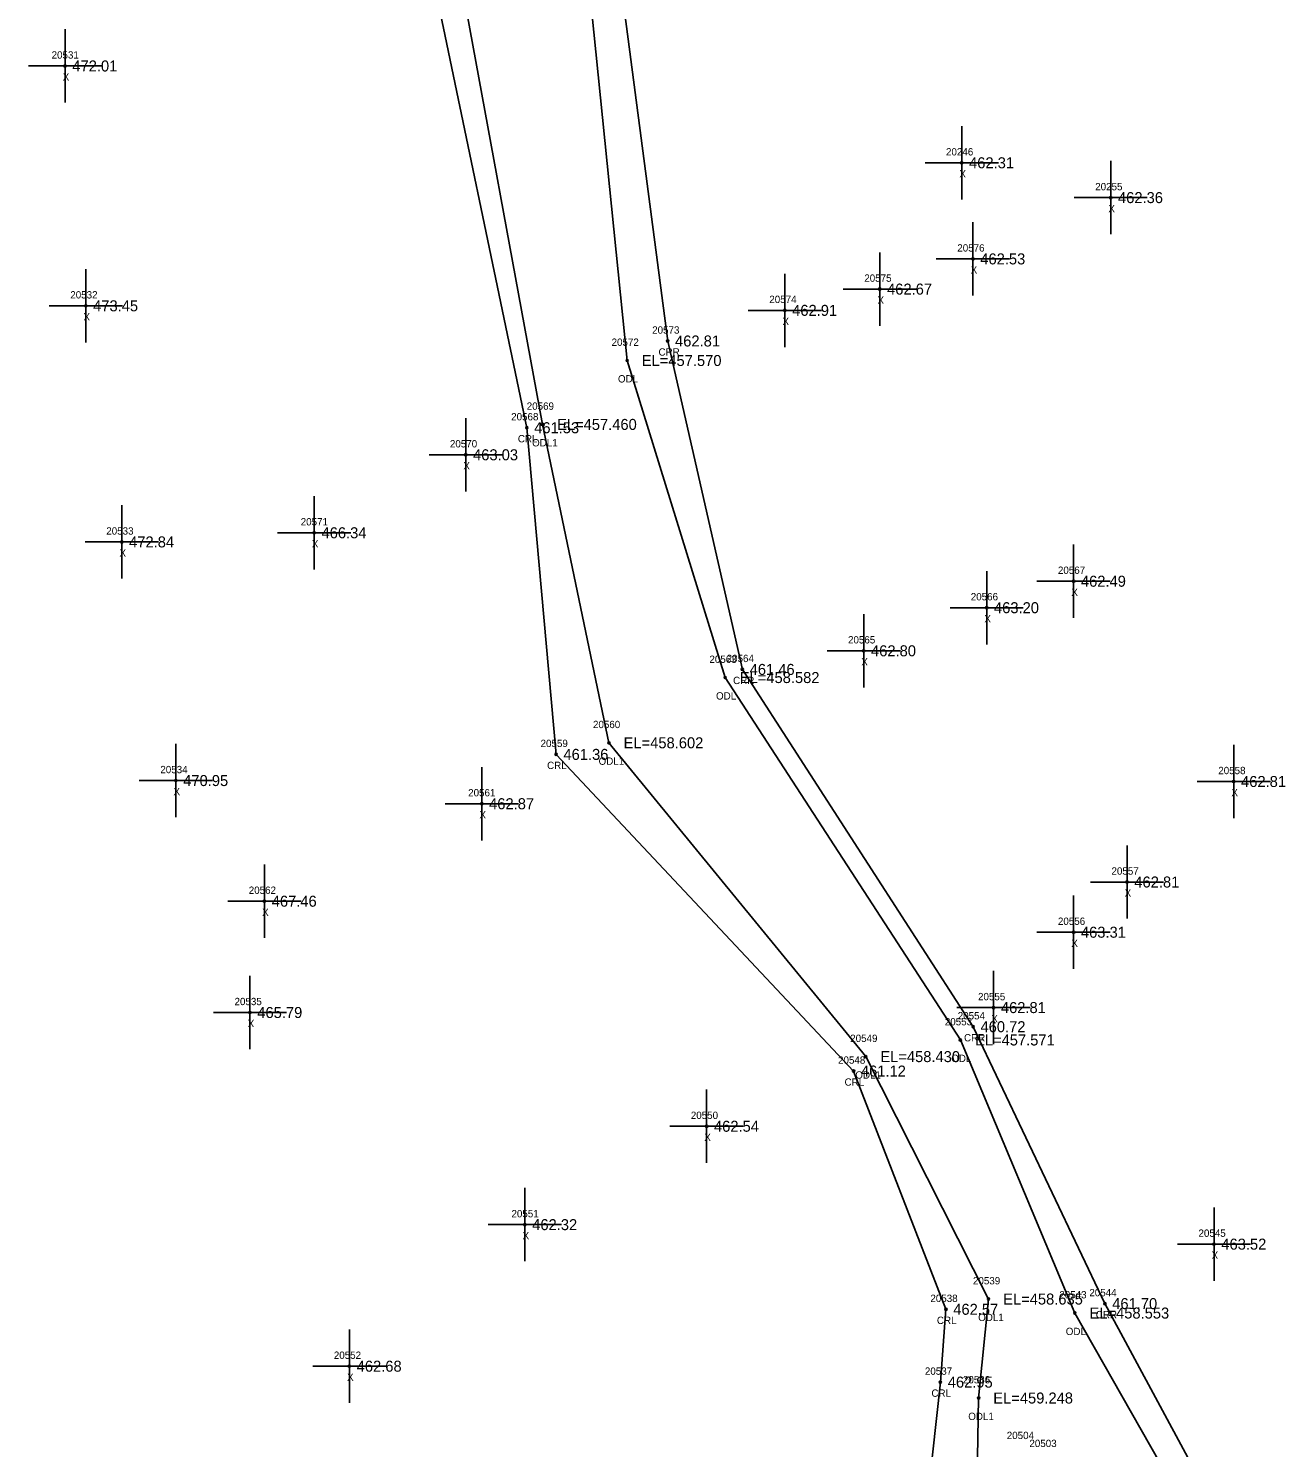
# Model space of a CAD drawing. Extents: x 1785066 to 1786589, y 770293 to 771312.
# Drawn here: x 1785739 to 1785910.5, y 770582.3 to 770775.9 of the extents above; entities that cross this region are included whole.
import ezdxf

# ---------------------------------------------------------------- set-up
doc = ezdxf.new("R2010")
doc.units = 0
for name, color, linetype in [('RD_EX_H2O', 7, 'Continuous'), ('RD_EX_H2O_txCode', 7, 'Continuous'), ('RD_EX_Misc', 7, 'Continuous'), ('RD_EX_Misc_txCode', 7, 'Continuous'), ('RD_EX_TX_H2O_ELEV', 7, 'Continuous'), ('RD_EX_TX_Misc_ELEV', 7, 'Continuous'), ('RD_SMD_Locator', 7, 'Continuous')]:
    doc.layers.add(name, color=color, linetype=linetype)

msp = doc.modelspace()

# ---------------------------------------------------------------- linework, layer by layer
at = {"layer": 'RD_EX_H2O'}
for points in [[(1785811.86, 770507.25), (1785839.19, 770536.83), (1785857.09, 770560.81), (1785861.18, 770571.03), (1785863.41, 770591.28), (1785864.16, 770601.21), (1785851.56, 770633.71), (1785810.97, 770676.91), (1785806.98, 770721.47), (1785793.39, 770786.72), (1785796.81, 770824.03), (1785795.63, 770828.98)], [(1785996.34, 770328.69), (1785988.37, 770343.77), (1785978.71, 770369.85), (1785965.55, 770429.48), (1785948.02, 770485.76), (1785915.42, 770547.17), (1785885.85, 770601.99), (1785867.88, 770639.76), (1785836.38, 770688.5), (1785826.2, 770733.3), (1785818.95, 770788.69), (1785812.88, 770814.19), (1785823.4, 770822.64)], [(1785815.41, 770505.36), (1785842.99, 770534.37), (1785860.53, 770556.3), (1785868.3, 770570.17), (1785868.62, 770589.11), (1785869.97, 770602.61), (1785853.21, 770635.68), (1785818.18, 770678.49), (1785809.1, 770721.92), (1785797.13, 770787.08)], [(1785994.72, 770327.79), (1785985.4, 770344.24), (1785977.02, 770368.92), (1785961.9, 770428.77), (1785944.95, 770484.4), (1785912.86, 770545.98), (1785881.75, 770600.7), (1785866.13, 770637.95), (1785834.03, 770687.39), (1785820.66, 770730.64), (1785814.87, 770787.58)]]:
    msp.add_lwpolyline(points, dxfattribs=at)
at = {"layer": 'RD_EX_Misc'}
for p, q in [((1785743.96, 770765.82), (1785743.96, 770775.82)), ((1785738.96, 770770.82), (1785748.96, 770770.82)), ((1785866.32, 770752.61), (1785866.32, 770762.61)), ((1785861.32, 770757.61), (1785871.32, 770757.61)), ((1785886.64, 770747.86), (1785886.64, 770757.86)), ((1785881.64, 770752.86), (1785891.64, 770752.86)), ((1785867.85, 770739.5), (1785867.85, 770749.5)), ((1785855.13, 770735.38), (1785855.13, 770745.38)), ((1785862.85, 770744.5), (1785872.85, 770744.5)), ((1785746.8, 770733.1), (1785746.8, 770743.1)), ((1785842.18, 770732.48), (1785842.18, 770742.48)), ((1785850.13, 770740.38), (1785860.13, 770740.38)), ((1785741.8, 770738.1), (1785751.8, 770738.1)), ((1785837.18, 770737.48), (1785847.18, 770737.48)), ((1785798.64, 770712.78), (1785798.64, 770722.78)), ((1785793.64, 770717.78), (1785803.64, 770717.78)), ((1785751.71, 770700.89), (1785751.71, 770710.89)), ((1785777.96, 770702.14), (1785777.96, 770712.14)), ((1785772.96, 770707.14), (1785782.96, 770707.14)), ((1785746.71, 770705.89), (1785756.71, 770705.89)), ((1785881.58, 770695.53), (1785881.58, 770705.53)), ((1785869.72, 770691.92), (1785869.72, 770701.92)), ((1785876.58, 770700.53), (1785886.58, 770700.53)), ((1785852.94, 770686.04), (1785852.94, 770696.04)), ((1785864.72, 770696.92), (1785874.72, 770696.92)), ((1785847.94, 770691.04), (1785857.94, 770691.04)), ((1785759.09, 770668.34), (1785759.09, 770678.34)), ((1785903.43, 770668.21), (1785903.43, 770678.21)), ((1785800.83, 770665.18), (1785800.83, 770675.18)), ((1785754.09, 770673.34), (1785764.09, 770673.34)), ((1785898.43, 770673.21), (1785908.43, 770673.21)), ((1785795.83, 770670.18), (1785805.83, 770670.18)), ((1785888.87, 770654.5), (1785888.87, 770664.5)), ((1785771.17, 770651.88), (1785771.17, 770661.88)), ((1785883.87, 770659.5), (1785893.87, 770659.5)), ((1785766.17, 770656.88), (1785776.17, 770656.88)), ((1785881.58, 770647.65), (1785881.58, 770657.65)), ((1785876.58, 770652.65), (1785886.58, 770652.65)), ((1785870.66, 770637.37), (1785870.66, 770647.37)), ((1785769.2, 770636.7), (1785769.2, 770646.7)), ((1785764.2, 770641.7), (1785774.2, 770641.7)), ((1785865.66, 770642.37), (1785875.66, 770642.37)), ((1785831.51, 770621.18), (1785831.51, 770631.18)), ((1785826.51, 770626.18), (1785836.51, 770626.18)), ((1785806.71, 770607.76), (1785806.71, 770617.76)), ((1785900.74, 770605.1), (1785900.74, 770615.1)), ((1785801.71, 770612.76), (1785811.71, 770612.76)), ((1785895.74, 770610.1), (1785905.74, 770610.1)), ((1785782.76, 770588.45), (1785782.76, 770598.45)), ((1785777.76, 770593.45), (1785787.76, 770593.45))]:
    msp.add_line(p, q, dxfattribs=at)
at = {"layer": 'RD_SMD_Locator'}
for centre in [(1785743.96, 770770.82), (1785866.32, 770757.61), (1785886.64, 770752.86), (1785867.85, 770744.5), (1785855.13, 770740.38), (1785746.8, 770738.1), (1785842.18, 770737.48), (1785826.2, 770733.3), (1785820.66, 770730.64), (1785806.98, 770721.47), (1785809.1, 770721.92), (1785798.64, 770717.78), (1785777.96, 770707.14), (1785751.71, 770705.89), (1785881.58, 770700.53), (1785869.72, 770696.92), (1785852.94, 770691.04), (1785836.38, 770688.5), (1785834.03, 770687.39), (1785818.18, 770678.49), (1785810.97, 770676.91), (1785759.09, 770673.34), (1785903.43, 770673.21), (1785800.83, 770670.18), (1785888.87, 770659.5), (1785771.17, 770656.88), (1785881.58, 770652.65), (1785769.2, 770641.7), (1785870.66, 770642.37), (1785867.88, 770639.76), (1785866.13, 770637.95), (1785853.21, 770635.68), (1785851.56, 770633.71), (1785831.51, 770626.18), (1785806.71, 770612.76), (1785900.74, 770610.1), (1785869.97, 770602.61), (1785864.16, 770601.21), (1785881.75, 770600.7), (1785885.85, 770601.99), (1785782.76, 770593.45), (1785863.41, 770591.28), (1785868.62, 770589.11)]:
    msp.add_circle(centre, 0.15, dxfattribs=at)

# ---------------------------------------------------------------- texts
at = {"layer": 'RD_EX_H2O_txCode'}
for s, p in [('20573', (1785824.08, 770734.3)), ('20572', (1785818.54, 770732.64)), ('CRR', (1785824.94, 770731.3)), ('ODL', (1785819.41, 770727.64)), ('20569', (1785806.96, 770723.92)), ('20568', (1785804.84, 770722.47)), ('CRL', (1785805.75, 770719.47)), ('ODL1', (1785807.69, 770718.92)), ('20563', (1785831.89, 770689.39)), ('20564', (1785834.24, 770689.5)), ('CRR', (1785835.12, 770686.5)), ('ODL', (1785832.79, 770684.39)), ('20560', (1785816, 770680.49)), ('20559', (1785808.85, 770677.91)), ('ODL1', (1785816.77, 770675.49)), ('CRL', (1785809.74, 770674.91)), ('20554', (1785865.77, 770640.76)), ('20553', (1785864.01, 770639.95)), ('20549', (1785851.1, 770637.68)), ('CRR', (1785866.63, 770637.76)), ('20548', (1785849.44, 770634.71)), ('ODL', (1785864.89, 770634.95)), ('ODL1', (1785851.8, 770632.68)), ('CRL', (1785850.33, 770631.71)), ('20539', (1785867.85, 770604.61)), ('20538', (1785862.04, 770602.21)), ('20543', (1785879.63, 770602.7)), ('20544', (1785883.73, 770602.99)), ('ODL1', (1785868.56, 770599.61)), ('CRR', (1785884.6, 770599.99)), ('CRL', (1785862.93, 770599.21)), ('ODL', (1785880.51, 770597.7)), ('20537', (1785861.29, 770592.28)), ('20536', (1785866.48, 770591.11)), ('CRL', (1785862.18, 770589.28)), ('ODL1', (1785867.21, 770586.11)), ('20504', (1785872.46, 770583.51)), ('20503', (1785875.55, 770582.42))]:
    msp.add_text(s, height=1, dxfattribs=at).set_placement(p)
at = {"layer": 'RD_EX_Misc_txCode'}
for s, p in [('20531', (1785742.13, 770771.82)), ('X', (1785743.65, 770768.82)), ('20246', (1785864.17, 770758.61)), ('X', (1785866, 770755.61)), ('20255', (1785884.53, 770753.86)), ('X', (1785886.33, 770750.86)), ('20576', (1785865.71, 770745.5)), ('20575', (1785853.02, 770741.38)), ('X', (1785867.54, 770742.5)), ('20532', (1785744.68, 770739.1)), ('20574', (1785840.06, 770738.48)), ('X', (1785854.82, 770738.38)), ('X', (1785746.48, 770736.1)), ('X', (1785841.86, 770735.48)), ('20570', (1785796.48, 770718.78)), ('X', (1785798.32, 770715.78)), ('20571', (1785776.12, 770708.14)), ('20533', (1785749.59, 770706.89)), ('X', (1785777.64, 770705.14)), ('X', (1785751.4, 770703.89)), ('20567', (1785879.44, 770701.53)), ('X', (1785881.27, 770698.53)), ('20566', (1785867.55, 770697.92)), ('X', (1785869.41, 770694.92)), ('20565', (1785850.8, 770692.04)), ('X', (1785852.62, 770689.04)), ('20534', (1785756.97, 770674.34)), ('20558', (1785901.32, 770674.21)), ('X', (1785758.77, 770671.34)), ('20561', (1785798.97, 770671.18)), ('X', (1785903.12, 770671.21)), ('X', (1785800.51, 770668.18)), ('20557', (1785886.75, 770660.5)), ('20562', (1785769.03, 770657.88)), ('X', (1785888.55, 770657.5)), ('X', (1785770.86, 770654.88)), ('20556', (1785879.44, 770653.65)), ('X', (1785881.27, 770650.65)), ('20535', (1785767.09, 770642.7)), ('20555', (1785868.54, 770643.37)), ('X', (1785870.35, 770640.37)), ('X', (1785768.89, 770639.7)), ('20550', (1785829.35, 770627.18)), ('X', (1785831.19, 770624.18)), ('20551', (1785804.88, 770613.76)), ('20545', (1785898.62, 770611.1)), ('X', (1785806.4, 770610.76)), ('X', (1785900.42, 770608.1)), ('20552', (1785780.64, 770594.45)), ('X', (1785782.45, 770591.45))]:
    msp.add_text(s, height=1, dxfattribs=at).set_placement(p)
at = {"layer": 'RD_EX_TX_H2O_ELEV'}
for s, p in [('462.81', (1785827.2, 770732.55)), ('EL=457.570', (1785822.66, 770729.89)), ('EL=457.460', (1785811.1, 770721.17)), ('461.53', (1785807.98, 770720.72)), ('EL=458.582', (1785836.03, 770686.64)), ('461.46', (1785837.38, 770687.75)), ('EL=458.602', (1785820.18, 770677.74)), ('461.36', (1785811.97, 770676.16)), ('460.72', (1785868.88, 770639.01)), ('EL=457.571', (1785868.13, 770637.2)), ('EL=458.430', (1785855.21, 770634.93)), ('461.12', (1785852.56, 770632.96)), ('EL=458.635', (1785871.97, 770601.86)), ('461.70', (1785886.85, 770601.24)), ('462.57', (1785865.16, 770600.46)), ('EL=458.553', (1785883.75, 770599.95)), ('462.95', (1785864.41, 770590.53)), ('EL=459.248', (1785870.62, 770588.36))]:
    msp.add_text(s, height=1.5, dxfattribs=at).set_placement(p)
at = {"layer": 'RD_EX_TX_Misc_ELEV'}
for s, p in [('472.01', (1785744.96, 770770.07)), ('462.31', (1785867.32, 770756.86)), ('462.36', (1785887.64, 770752.11)), ('462.53', (1785868.85, 770743.75)), ('462.67', (1785856.13, 770739.63)), ('473.45', (1785747.8, 770737.35)), ('462.91', (1785843.18, 770736.73)), ('463.03', (1785799.64, 770717.03)), ('466.34', (1785778.96, 770706.39)), ('472.84', (1785752.71, 770705.14)), ('462.49', (1785882.58, 770699.78)), ('463.20', (1785870.72, 770696.17)), ('462.80', (1785853.94, 770690.29)), ('470.95', (1785760.09, 770672.59)), ('462.81', (1785904.43, 770672.46)), ('462.87', (1785801.83, 770669.43)), ('462.81', (1785889.87, 770658.75)), ('467.46', (1785772.17, 770656.13)), ('463.31', (1785882.58, 770651.9)), ('462.81', (1785871.66, 770641.62)), ('465.79', (1785770.2, 770640.95)), ('462.54', (1785832.51, 770625.43)), ('462.32', (1785807.71, 770612.01)), ('463.52', (1785901.74, 770609.35)), ('462.68', (1785783.76, 770592.7))]:
    msp.add_text(s, height=1.5, dxfattribs=at).set_placement(p)

doc.saveas('drawing.dxf')
